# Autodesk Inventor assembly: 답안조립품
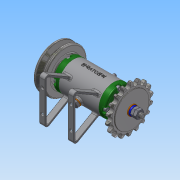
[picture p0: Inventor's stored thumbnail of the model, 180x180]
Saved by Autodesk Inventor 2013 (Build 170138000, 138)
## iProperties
Created: 2016-03
Part Number: 답안조립품
Document SubType Name: Assembly
Designer: Administrator
Author: Administrator
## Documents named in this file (16)
- C:\Users\Administrator\Desktop\460308V1004\답안조립품.iam
- C:\Users\Administrator\Desktop\460308V1004\V벨트풀리.ipt
- C:\Users\Administrator\Desktop\460308V1004\너트 M 8.ipt
- C:\Users\Administrator\Desktop\460308V1004\니플 M 6 x 0.75.ipt
- C:\Users\Administrator\Desktop\460308V1004\베어링 15 x 32 x 9.ipt
- C:\Users\Administrator\Desktop\460308V1004\본체.ipt
- C:\Users\Administrator\Desktop\460308V1004\볼트 M 6 x 8.ipt
- C:\Users\Administrator\Desktop\460308V1004\볼트 M4 x 12.ipt
- C:\Users\Administrator\Desktop\460308V1004\스프로킷.ipt
- C:\Users\Administrator\Desktop\460308V1004\스프링와셔 8.ipt
- C:\Users\Administrator\Desktop\460308V1004\오일 실 15 25 7.ipt
- C:\Users\Administrator\Desktop\460308V1004\와셔 6x11.5.ipt
- C:\Users\Administrator\Desktop\460308V1004\와셔 8x17.ipt
- C:\Users\Administrator\Desktop\460308V1004\축.ipt
- C:\Users\Administrator\Desktop\460308V1004\커버.ipt
- C:\Users\Administrator\Desktop\460308V1004\키 3 x 3 x 12.ipt
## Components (11 placed, 3 different names)
1. V벨트풀리:1
2. KS B 2023 6002 - 15 x 32 x 9:1
3. KS B 2023 6002 - 15 x 32 x 9:2
4. ISO 4762 M4 x 12:1
5. ISO 4762 M4 x 12:2
6. ISO 4762 M4 x 12:3
7. ISO 4762 M4 x 12:4
8. ISO 4762 M4 x 12:5
9. ISO 4762 M4 x 12:6
10. ISO 4762 M4 x 12:7
11. ISO 4762 M4 x 12:8
